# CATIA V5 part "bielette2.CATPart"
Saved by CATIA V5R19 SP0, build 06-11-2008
Part number: bielette2
Bounding box of the stored display mesh (mm): x -19.964 to 129.964, y 335.036 to 429.964, z -45 to 45
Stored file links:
  C:\Users\Thibaud\Desktop\IFMA\thinkmotion\IAO\modele_catia\bielette2.CATPart
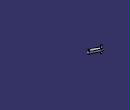
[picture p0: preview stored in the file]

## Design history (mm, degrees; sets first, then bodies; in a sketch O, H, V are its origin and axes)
Body1 (main body)
  Plane1: stored without definition
  Line1: stored without definition
  Line2: stored without definition
  Line3 "axe_pivot_bielette2_sabot1": stored without definition
  Line4 "axe_pivot_bielette2_levier": stored without definition
  DatumSurface1
  Plane2: stored without definition
  Sketch1 on Plane1, origin (0, 0, 0), H (1, 0, 0), V (0, 1, 0)
    point P1 (8.9443, 427.8885)
    line L1 (8.9443, 427.8885) -> (118.9443, 372.8885)
    arc A1 centre (110, 355) radius 20 from (118.9443, 372.8885) to (101.0557, 337.1115) cw
    point P3 (110, 355)
    line L2 (101.0557, 337.1115) -> (-8.9443, 392.1115)
    arc A2 centre (0, 410) radius 20 from (-8.9443, 392.1115) to (8.9443, 427.8885) cw
    point P6 (0, 410)
    point P7 (8.9443, 427.8885)
    reference projected line E1 (0, 410) -> (110, 355) from Line2
    reference projected point E2 (110, 355) from Line3
    reference projected point E3 (0, 410) from Line4
    radius A1 = 20
    tangency: A1 L1, L2 A1, A2 L1, A2 L2
    parallelism: L1 E1, L2 L1
    coincidence: P3 E2, P6 E3, P7 P1
  Pad1: profile Sketch1, direction (0, 0, 1), length 15, mirrored extent
  Line5 "axe_pivot_bielette2_sabot1": stored without definition
  Line6 "axe_pivot_bielette2_levier": stored without definition
  Plane3: stored without definition
  Sketch2 on Plane2, origin (0, 0, 0), H (1, 0, 0), V (0, 1, 0)
    circle A1 centre (110, 355) radius 10
    point P1 (110, 355)
    reference projected point E1 (110, 355) from Line5
    radius A1 = 10
    coincidence: P1 E1
  Pad2: profile Sketch2, direction (0, 0, 1), length 29, mirrored extent
  Line7 "axe_pivot_bielette2_levier": stored without definition
  Sketch3 on Plane3, origin (0, 0, 0), H (1, 0, 0), V (0, 1, 0)
    circle A1 centre (0, 410) radius 10
    point P1 (0, 410)
    reference projected point E1 (0, 410) from Line7
    radius A1 = 10
    coincidence: P1 E1
  Pad3: profile Sketch3, direction (0, 0, 1), length 45, mirrored extent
